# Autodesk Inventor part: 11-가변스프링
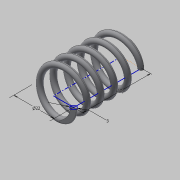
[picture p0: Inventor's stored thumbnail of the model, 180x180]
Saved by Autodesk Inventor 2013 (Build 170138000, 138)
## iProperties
Created: 2015-02
Part Number: 11-가변스프링
Material: 강철, 탄소
Document SubType Name: Modeling
Designer: Administrator
Density: 7.87 g/cm^3
Mass: 18.7444 g
Surface Area: 32.4012 cm^2
Volume: 2.38175 cm^3
Author: Administrator
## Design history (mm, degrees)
sketch "스케치1"
  geometry: L1 (0, 0)-(11, 0); L2 (11, 0)-(11, 25.508); L3 (11, 25.508)-(0, 25.508); L4 (0, 25.508)-(0, 0); C1 r 1.5 at (11, 0)
  constraints: 8 end point, 2 parallel, 1 centre point, 1 coincident, 1 horizontal, 1 perpendicular
  dimensions: "d0" = 25.50829 distance of L1.end L2.end (derived); "d2" = 22 diameter of L2 L4; "d3" = 3 diameter of C1
feature "코일1" sketch "스케치1" pitch "d4" = 10; turns "d6" = 5; dims "d5" = 25.50829 (= d0), "d7" = 0, angle "d8" = 90 deg, angle "d9" = 90 deg, "d10" = 0, "d11" = 0
node "작업 평면1"
sketch "스케치2"
  geometry: L1 (-12.5, 0)-(-9.5, 0) reference; L2 (-12.5, 0)-(-9.5, 0) reference; 1 further point
  constraints: 2 horizontal alignment
extrude "돌출1" cut sketch "스케치2" distance "d13" = 10; taper "d14" = 0 deg
node "작업 평면2"
sketch "스케치3"
  geometry: L1 (-9.5, 0)-(-12.5, 0) reference; 1 further point
  constraints: 1 horizontal alignment
extrude "돌출2" cut sketch "스케치3" distance "d16" = 10; taper "d17" = 0 deg
node "솔리드1"
node "절단 모서리 투영1"
node "절단 모서리 투영2"
node "절단 모서리 투영3"
other parameters: "d12" = 0, "d15" = 25.50829 (= d0)
